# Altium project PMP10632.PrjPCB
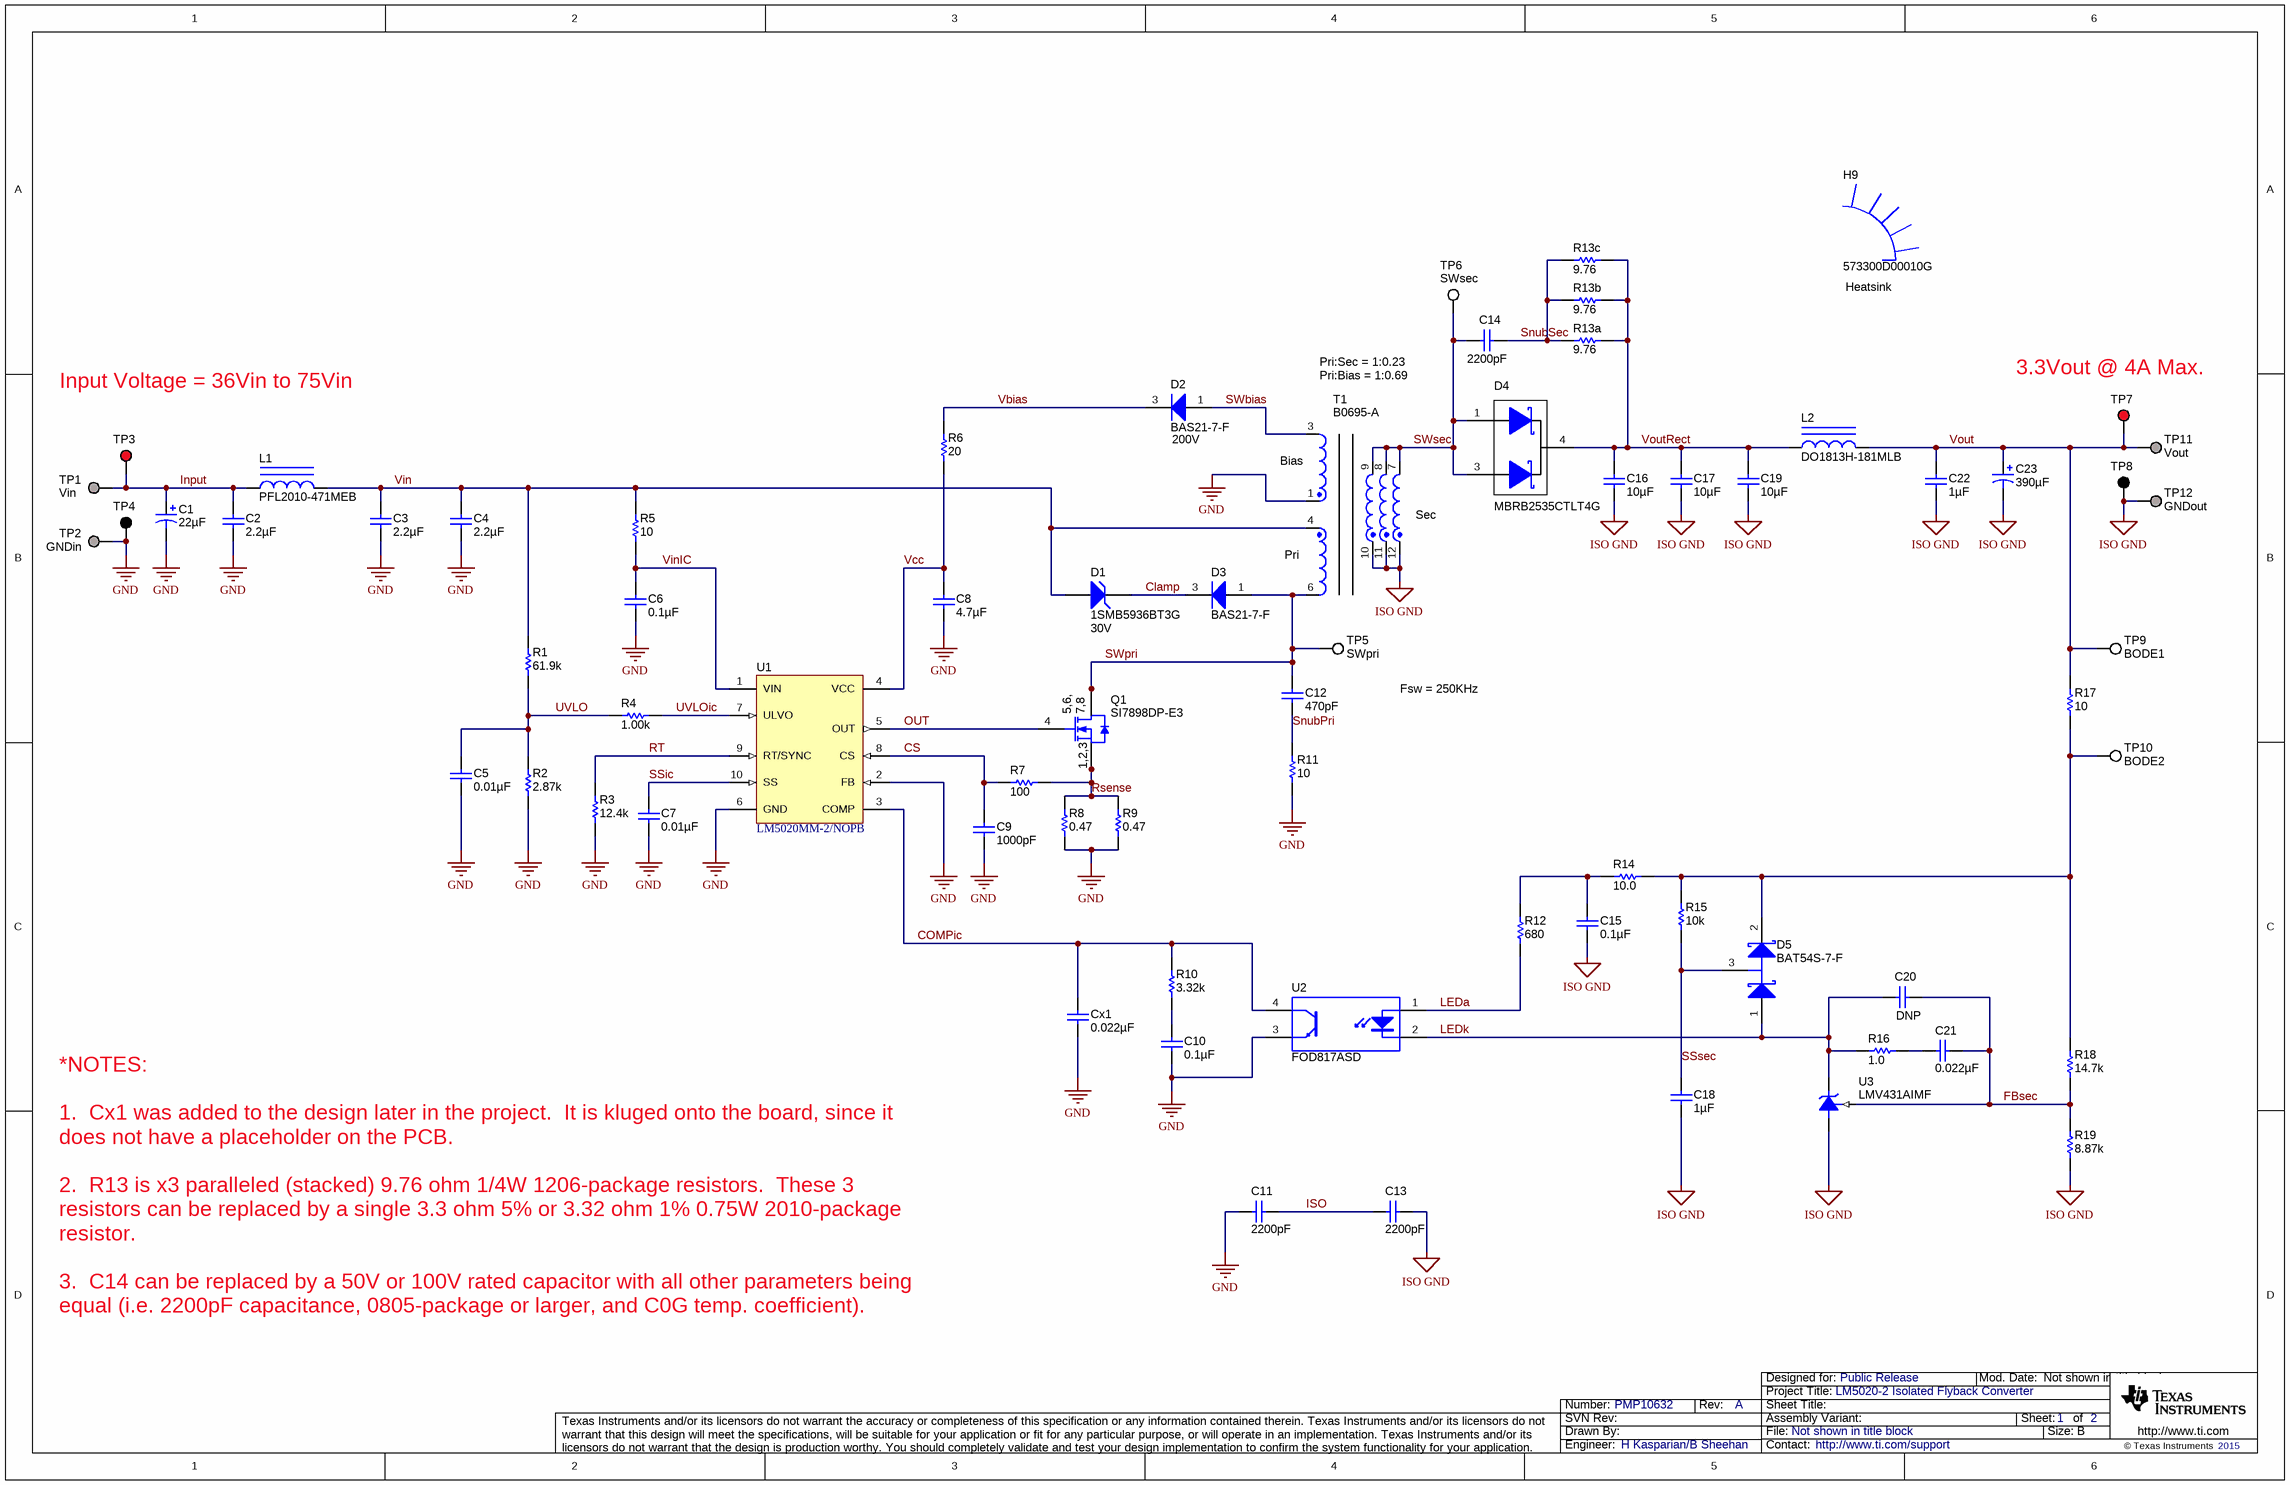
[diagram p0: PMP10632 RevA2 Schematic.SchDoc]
CopyrightYear: 2015; PCB_Layout: H Kasparian; PCB_Rev: A; PRJ_Customer: Public Release; PRJ_Engineer: H Kasparian/B Sheehan; PRJ_Number: PMP10632; PRJ_Title: LM5020-2 Isolated Flyback Converter; SCH_Rev: A; TechSupport: http://www.ti.com/support
2 sheets, 89 parts. Net scope: global (net labels, ports and power ports of the same name join across sheets).
Board file: PMP10632.PcbDoc
Sheets:
  PMP10632 RevA2 Schematic.SchDoc
  PMP10632_Hardware_ANSI-B.SchDoc

## Sheet PMP10632 RevA2 Schematic.SchDoc
size 431 x 279 mm; Date: Not shown in title block; ApprovedBy: Not shown in title block; CheckedBy: Not shown in title block; Author: Not shown in title block; CompanyName: Not shown in title block; Engineer: Not shown in title block; Organization: Not shown in title block; Address1: Not shown in title block; Address2: Not shown in title block; Address3: Not shown in title block; Address4: Not shown in title block; DocumentNumber: 1; Revision: A2; SheetNumber: 1; SheetTotal: 2; PageSetup: Record=PageOptions¦CenterHorizontal=True¦CenterVertical=True¦PrintScale=1.00¦XCorrection=1.00¦YCorrection=1.00¦PrintKind=0¦BorderSize=5000000¦LeftOffset=0¦BottomOffset=0¦Orientation=2¦PaperLength=1000¦PaperWidth=1000¦Scale=100¦PaperSource=15¦PrintQuality=600¦MediaType=1¦DitherType=10¦PaperKind=Letter¦PrintScaleMode=1

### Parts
C1  ValueDisplayed: 22µF  [SM_RADIAL_F]  (hidden comment: EEE-FK2A220P)
C2  ValueDisplayed: 2.2µF  [1210]  (hidden comment: GRM32ER72A225KA35L)
C3  ValueDisplayed: 2.2µF  [1210]  (hidden comment: GRM32ER72A225KA35L)
C4  ValueDisplayed: 2.2µF  [1210]  (hidden comment: GRM32ER72A225KA35L)
C5  ValueDisplayed: 0.01µF  [0603]  (hidden comment: GRM188R71E103KA01D)
C6  ValueDisplayed: 0.1µF  [0805_HV]  (hidden comment: C0805C104K1RACTU)
C7  ValueDisplayed: 0.01µF  [0603]  (hidden comment: GRM188R71E103KA01D)
C8  ValueDisplayed: 4.7µF  [0805_HV]  (hidden comment: GRM21BR71C475KA73L)
C9  ValueDisplayed: 1000pF  [0603]  (hidden comment: C0603C102J5GAC)
C10  ValueDisplayed: 0.1µF  [0603]  (hidden comment: 06035C104KAT2A)
C11  ValueDisplayed: 2200pF  [1206]  (hidden comment: VJ1206Y222KXGAT5Z)
C12  ValueDisplayed: 470pF  [0805_HV]  (hidden comment: GRM2165C2A471JA01D)
C13  ValueDisplayed: 2200pF  [1206]  (hidden comment: VJ1206Y222KXGAT5Z)
C14  2200pF  [TBD]
C15  ValueDisplayed: 0.1µF  [0603]  (hidden comment: GRM188R71E104KA01D)
C16  ValueDisplayed: 10µF  [1206]  (hidden comment: GRM31CR71E106KA12L)
C17  ValueDisplayed: 10µF  [1206]  (hidden comment: GRM31CR71E106KA12L)
C18  ValueDisplayed: 1µF  [0603]  (hidden comment: GRM188R71A105KA61D)
C19  ValueDisplayed: 10µF  [1206]  (hidden comment: GRM31CR71E106KA12L)
C20  DNP  [0603]
C21  ValueDisplayed: 0.022µF  [0603]  (hidden comment: GRM188R71H223KA01D)
C22  ValueDisplayed: 1µF  [0805_HV]  (hidden comment: GRM219R71E105KA88D)
C23  ValueDisplayed: 390µF  [CAPAE1030X1080]  (hidden comment: EEE-FPV391UAP)
Cx1  ValueDisplayed: 0.022µF  [0603]  (hidden comment: C0603C223K5RACTU)
D1  1SMB5936BT3G  value 30V  [SMB]
D2  BAS21-7-F  value 200V  [SOT-23]
D3  BAS21-7-F  [SOT-23]
D4  MBRB2535CTLT4G  [DDPAK]
D5  BAT54S-7-F  [SOT-23]
H9  573300D00010G  [HEATSINK_573300D00010G]
L1  PFL2010-471MEB  [PFL2010]
L2  DO1813H-181MLB  [DO1813H]
Q1  SI7898DP-E3  [PowerPAK_SO-8]
R1  ValueDisplayed: 61.9k  [1206]  (hidden comment: CRCW120661K9FKEA)
R2  ValueDisplayed: 2.87k  [0603]  (hidden comment: CRCW06032K87FKEA)
R3  ValueDisplayed: 12.4k  [0603]  (hidden comment: CRCW060312K4FKEA)
R4  ValueDisplayed: 1.00k  [0603]  (hidden comment: CRCW06031K00FKEA)
R5  ValueDisplayed: 10  [0805_HV]  (hidden comment: CRCW080510R0JNEA)
R6  ValueDisplayed: 20  [0805_HV]  (hidden comment: CRCW080520R0JNEA)
R7  ValueDisplayed: 100  [0603]  (hidden comment: CRCW0603100RFKEA)
R8  ValueDisplayed: 0.47  [1206]  (hidden comment: ERJ-8RQFR47V)
R9  ValueDisplayed: 0.47  [1206]  (hidden comment: ERJ-8RQFR47V)
R10  ValueDisplayed: 3.32k  [0603]  (hidden comment: CRCW06033K32FKEA)
R11  ValueDisplayed: 10  [2512]  (hidden comment: CRCW251210R0JNEG)
R12  ValueDisplayed: 680  [0603]  (hidden comment: CRCW0603680RJNEA)
R13a  ValueDisplayed: 9.76  [1206]  (hidden comment: CRCW12069R76FKEA)
R13b  ValueDisplayed: 9.76  [1206]  (hidden comment: CRCW12069R76FKEA)
R13c  ValueDisplayed: 9.76  [1206]  (hidden comment: CRCW12069R76FKEA)
R14  ValueDisplayed: 10.0  [0603]  (hidden comment: CRCW060310R0FKEA)
R15  ValueDisplayed: 10k  [0603]  (hidden comment: CRCW060310K0JNEA)
R16  ValueDisplayed: 1.0  [0603]  (hidden comment: CRCW06031R00JNEA)
R17  ValueDisplayed: 10  [0805_HV]  (hidden comment: CRCW080510R0JNEA)
R18  ValueDisplayed: 14.7k  [0603]  (hidden comment: CRCW060314K7FKEA)
R19  ValueDisplayed: 8.87k  [0603]  (hidden comment: CRCW06038K87FKEA)
T1  B0695-A  [B0695-A]
TP1  Vin  [Keystone1593-2]
TP2  GNDin  [Keystone1593-2]
TP3  (no value)  [Keystone5010]
TP4  (no value)  [Keystone5011]
TP5  SWpri  [Keystone5012]
TP6  SWsec  [Keystone5012]
TP7  (no value)  [Keystone5010]
TP8  (no value)  [Keystone5011]
TP9  BODE1  [Keystone5012]
TP10  BODE2  [Keystone5012]
TP11  Vout  [Keystone1593-2]
TP12  GNDout  [Keystone1593-2]
U1  LM5020MM-2/NOPB  [MUB10A_N]
U2  FOD817ASD  [N04C]
U3  LMV431AIMF  [MF03A_N]

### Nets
GND: C1.2(-) C2.2 C3.2 C4.2 C5.2 C6.2 C7.2 C8.2 C9.2 C10.2 C11.2 Cx1.2 R2.1 R3.1 R8.1 R9.1 R11.1 T1.1 TP2.1 TP4.1 U1.2(FB) U1.6(GND) U2.3(E)
ISO GND: C13.1 C15.2 C16.2 C17.2 C18.2 C19.2 C22.2 C23.2(-) R19.1 T1.10 T1.11 T1.12 TP8.1 TP12.1 U3.3(A)
Clamp: D1.1(K) D3.3(K)
COMPic: Cx1.1 R10.2 U1.3(COMP) U2.4(C)
CS: C9.1 R7.1 U1.8(CS)
FBsec: C20.1 C21.2 R18.1 R19.2 U3.1(REF)
Input: C1.1(+) C2.1 L1.1 TP1.1 TP3.1
ISO: C11.1 C13.2
LEDa: R12.1 U2.1(A)
LEDk: C20.2 D5.1(A) R16.2 U2.2(K) U3.2(K)
OUT: Q1.4(G) U1.5(OUT)
Rsense: Q1.1(S) Q1.2(S) Q1.3(S) R7.2 R8.2 R9.2
RT: R3.2 U1.9(RT/SYNC)
SnubPri: C12.2 R11.2
SnubSec: C14.1 R13a.2 R13b.2 R13c.2
SSic: C7.1 U1.10(SS)
SSsec: C18.1 D5.3(C) R15.1
SWbias: D2.1(A) T1.3
SWpri: C12.1 D3.1(A) Q1.5(D) Q1.6(D) Q1.7(D) Q1.8(D) Q1.9(D) T1.6 TP5.1
SWsec: C14.2 D4.1(A) D4.3(A) T1.7 T1.8 T1.9 TP6.1
UVLO: C5.1 R1.1 R2.2 R4.1
UVLOic: R4.2 U1.7(ULVO)
Vbias: D2.3(K) R6.1
Vcc: C8.1 R6.2 U1.4(VCC)
Vin: C3.1 C4.1 D1.2(A) L1.2 R1.2 R5.2 T1.4
VinIC: C6.1 R5.1 U1.1(VIN)
Vout: C22.1 C23.1(+) L2.2 R17.2 TP7.1 TP9.1 TP11.1
VoutRect: C16.1 C17.1 C19.1 D4.4(K) L2.1 R13a.1 R13b.1 R13c.1
NetC10_1: C10.1 R10.1
NetC15_1: C15.1 R12.2 R14.2
NetC21_1: C21.1 R16.1
NetD5_2: D5.2(K) R14.1 R15.2 R17.1 R18.2 TP10.1

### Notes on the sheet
- (near H9) Heatsink
- (near TP7) 3.3Vout @ 4A Max.
- Input Voltage = 36Vin to 75Vin
- Pri:Sec = 1:0.23
  Pri:Bias = 1:0.69
- (near T1) Bias
- (near T1) Pri
- (near T1) Sec
- Fsw = 250KHz
- *NOTES:
  1.  Cx1 was added to the design later in the project.  It is kluged onto the board, since it does not have a placeholder on the PCB.
  2.  R13 is x3 paralleled (stacked) 9.76 ohm 1/4W 1206-package resistors.  These 3 resistors can be replaced by a single 3.3 ohm 5% or 3.32 ohm 1% 0.75W 2010-package resistor.
  3.  C14 can be replaced by a 50V or 100V rated capacitor with all other parameters being equal (i.e. 2200pF capacitance, 0805-package or larger, and C0G temp. coefficient).

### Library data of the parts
C1 = EEE-FK2A220P: CAP, AL, 22 µF, 100 V, +/- 20%, 1.3 ohm, SMD; Manufacturer: Panasonic; Polarized: Y; CompType: Capacitor; Value: 22uF; U/M: EA; Cap_F: 0.000022; Tolerance_%: 20; Value1: 1.3 ohm; VDC_V: 100; Value2: 100V; ESR_ohm: 1.3; IRMS_A: 0.13; TaMin_C: -55; TaMax_C: 105; Cap_Case: F
C2-C4 = GRM32ER72A225KA35L: CAP, CERM, 2.2 µF, 100 V, +/- 10%, X7R, 1210; Manufacturer: MuRata; Polarized: N; CompType: Capacitor; Value: 2.2uF; U/M: EA; Cap_F: 0.0000022; Tolerance_%: 10; ESR_ohm: 0.007; Value1: 0.007 ohm; VDC_V: 100; Value2: 100V; IRMS_A: 4.4; TaMin_C: -55; TaMax_C: 125
C5 C7 = GRM188R71E103KA01D: CAP, CERM, 0.01 µF, 25 V, +/- 10%, X7R, 0603; Manufacturer: MuRata; Polarized: N; CompType: Capacitor; Value: 0.01uF; U/M: EA; Cap_F: 0.00000001; Tolerance_%: 10; Value1: Unknown; VDC_V: 25; Value2: 25V; TaMin_C: -55; TaMax_C: 125
C6 = C0805C104K1RACTU: CAP, CERM, 0.1 µF, 100 V, +/- 10%, X7R, 0805; Manufacturer: Kemet; Polarized: N; CompType: Capacitor; Value: 0.1uF; U/M: EA; Cap_F: 0.0000001; Tolerance_%: 10; ESR_ohm: 0.064; Value1: 0.064 ohm; VDC_V: 100; Value2: 100V; IRMS_A: 1.64; TaMin_C: -55; TaMax_C: 125; Cap_Case: 0805
C8 = GRM21BR71C475KA73L: CAP, CERM, 4.7 µF, 16 V, +/- 10%, X7R, 0805; Manufacturer: MuRata; Polarized: N; CompType: Capacitor; Value: 4.7uF; U/M: EA; Cap_F: 0.0000047; Tolerance_%: 10; ESR_ohm: 0.006; Value1: 0.006 ohm; VDC_V: 16; Value2: 16V; TaMin_C: -55; TaMax_C: 125; Cap_Case: 0805
C9 = C0603C102J5GAC: CAP, CERM, 1000 pF, 50 V, +/- 5%, C0G/NP0, 0603; Manufacturer: Kemet; Polarized: N; CompType: Capacitor; Value: 1000pF; U/M: EA; Cap_F: 0.000000001; Tolerance_%: 5; Value1: Unknown; VDC_V: 50; Value2: 50V; TaMin_C: -55; TaMax_C: 125
C10 = 06035C104KAT2A: CAP, CERM, 0.1 µF, 50 V, +/- 10%, X7R, 0603; Manufacturer: AVX; Polarized: N; CompType: Capacitor; Value: 0.1uF; U/M: EA; Cap_F: 0.0000001; Tolerance_%: 10; Value1: Unknown; VDC_V: 50; Value2: 50V; TaMin_C: -55; TaMax_C: 125
C11 C13 = VJ1206Y222KXGAT5Z: CAP, CERM, 2200 pF, 1000 V, +/- 10%, X7R, 1206; Manufacturer: Vishay-Vitramon; Polarized: N; CompType: Capacitor; Value: 2200pF; U/M: EA; Cap_F: 0.0000000022; Tolerance_%: 10; Value1: Unknown; VDC_V: 1000; Value2: 1000V; TaMin_C: -55; TaMax_C: 125
C12 = GRM2165C2A471JA01D: CAP, CERM, 470 pF, 100 V, +/- 5%, C0G/NP0, 0805; Manufacturer: MuRata; Polarized: N; CompType: Capacitor; Value: 470pF; U/M: EA; Cap_F: 0.00000000047; Tolerance_%: 5; Value1: Unknown; VDC_V: 100; Value2: 100V; TaMin_C: -55; TaMax_C: 125; Cap_Case: 0805
C14 = Capacitor: CAP, CERM, 2200pF, 250V, C0G, 5%, 0805; Manufacturer: TDK; PartNumber: CGA4J3C0G2E222J; Polarized: N; U/M: EA
C15 = GRM188R71E104KA01D: CAP, CERM, 0.1 µF, 25 V, +/- 10%, X7R, 0603; Manufacturer: MuRata; Polarized: N; CompType: Capacitor; Value: 0.1uF; U/M: EA; Cap_F: 0.0000001; Tolerance_%: 10; Value1: Unknown; VDC_V: 25; Value2: 25V; TaMin_C: -55; TaMax_C: 125
C16 C17 C19 = GRM31CR71E106KA12L: CAP, CERM, 10 µF, 25 V, +/- 10%, X7R, 1206; Manufacturer: MuRata; Polarized: N; CompType: Capacitor; Value: 10uF; U/M: EA; Cap_F: 0.00001; Tolerance_%: 10; Value1: Unknown; VDC_V: 25; Value2: 25V; TaMin_C: -55; TaMax_C: 125; Cap_Case: 2220
C18 = GRM188R71A105KA61D: CAP, CERM, 1 µF, 10 V, +/- 10%, X7R, 0603; Manufacturer: MuRata; Polarized: N; CompType: Capacitor; Value: 1uF; U/M: EA; Cap_F: 0.000001; Tolerance_%: 10; ESR_ohm: 0.011; Value1: 0.011 ohm; Value2: 10V; TaMin_C: -55; TaMax_C: 125
C20 = GRM1885C1H101JA01D: CAP, CERM, 100 pF, 50 V, +/- 5%, C0G/NP0, 0603; Manufacturer: MuRata; Polarized: N; CompType: Capacitor; Value: 100pF; U/M: EA; Cap_F: 0.0000000001; Tolerance_%: 5; Value1: Unknown; VDC_V: 50; Value2: 50V; TaMin_C: -55; TaMax_C: 125
C21 = GRM188R71H223KA01D: CAP, CERM, 0.022 µF, 50 V, +/- 10%, X7R, 0603; Manufacturer: MuRata; Polarized: N; CompType: Capacitor; Value: 0.022uF; U/M: EA; Cap_F: 0.000000022; Tolerance_%: 10; Value1: Unknown; VDC_V: 50; Value2: 50V; TaMin_C: -55; TaMax_C: 125
C22 = GRM219R71E105KA88D: CAP, CERM, 1 µF, 25 V, +/- 10%, X7R, 0805; Manufacturer: MuRata; Polarized: N; CompType: Capacitor; Value: 1uF; U/M: EA; Cap_F: 0.000001; Tolerance_%: 10; Value1: Unknown; VDC_V: 25; Value2: 25V; TaMin_C: -55; TaMax_C: 125; Cap_Case: 0805
C23 = EEE-FPV391UAP: CAP, AL, 390 µF, 35 V, +/- 20%, 0.08 ohm, SMD; Manufacturer: Panasonic; Polarized: Y; CompType: Capacitor; Value: 390uF; U/M: EA; Cap_F: 0.00039; Tolerance_%: 20; VDC_V: 35; Value2: 35V; ESR_ohm: 0.08; IRMS_A: 0.85; TaMin_C: -55; TaMax_C: 105; Cap_Case: 10x10.2mm
Cx1 = C0603C223K5RACTU: CAP, CERM, 0.022 µF, 50 V, +/- 10%, X7R, 0603; Manufacturer: Kemet; Polarized: N; CompType: Capacitor; Value: 0.022uF; U/M: EA; Cap_F: 0.000000022; Tolerance_%: 10; Value1: Unknown; VDC_V: 50; Value2: 50V; TaMin_C: -55; TaMax_C: 125
D1 = 1SMB5936BT3G: Diode, Zener, 30 V, 550 mW, SMB; Manufacturer: ON Semiconductor; SymbolCreator: a0412235; U/M: EA; Power_W: 0.55; Vz_V: 30; Value1: 0.55W; RJA_CperW: 226
D2 = BAS21-7-F: Diode, Switching, 200 V, 0.2 A, SOT-23; Manufacturer: Diodes Inc.; U/M: EA; Vf_V: 1.25; Value1: 0.2A; Value2: 1.25V; Io_A: 0.2; Vr_V: 200; TJmax_C: 150; RJC_CperW: 500
D3 = BAS21-7-F: Diode, Switching, 200 V, 0.2 A, SOT-23; Manufacturer: Diodes Inc.; U/M: EA; Vf_V: 1.25; Value: 200V; Value1: 0.2A; Value2: 1.25V; Io_A: 0.2; Vr_V: 200; TJmax_C: 150; RJC_CperW: 500
D4 = MBRB2535CTLT4G: Diode, Schottky, 35 V, 25 A, DDPAK; Manufacturer: ON Semiconductor; U/M: EA; Vf_V: 0.55; Value: 35V; Value1: 25A; Value2: 0.55V; Io_A: 25; Vr_V: 35; TJmax_C: 125; RJC_CperW: 1
D5 = BAT54S-7-F: Diode, Schottky, 30 V, 0.2 A, SOT-23; Manufacturer: Diodes Inc.; U/M: EA; Vf_V: 0.65; Value: 30V; Value1: 0.2A; Value2: 0.65V; Io_A: 0.2; Vr_V: 30; TJmax_C: 125
H9 = 573300D00010G: Heatsink, DDPAK/TO-263, SMT; Manufacturer: Aavid; SymbolCreator: a0412235
L1 = PFL2010-471MEB: Inductor, Shielded, Composite, 470 nH, 1.8 A, 0.06 ohm, SMD; Manufacturer: Coilcraft; Value: 470nH; Ind_H: 470.0E-9; Imax_A: 1.8; Irms: 1.9A @ 40C rise; Isat: 1.8A @ 30% inductance drop; DCR_ohm: 0.06; Value2: 1.8A
L2 = DO1813H-181MLB: Inductor, Drum Core, Ferrite, 180 nH, 10 A, 0.003 ohm, SMD; Manufacturer: Coilcraft; Value: 180nH; Ind_H: 180.0E-9; Imax_A: 10; Irms: 10A @ 40C rise; Isat: 14A @ 30% inductance drop; DCR_ohm: 0.003; Value2: 10A
Q1 = SI7898DP-E3: MOSFET, N-CH, 150 V, 3 A, PowerPAK SO-8; Manufacturer: Vishay-Siliconix; Alternate Manufacturer: None; U/M: EA; ChType: N; Value: 150V; VdsMax_V: 150; Value1: 0.076 ohm; Rdson45_ohm: 0.076; Value2: 17 nC; QgTyp_nC: 17; Vgs_V: 20; IdsMax_A: 3
R1 = CRCW120661K9FKEA: RES, 61.9 k, 1%, 0.25 W, 1206; Manufacturer: Vishay-Dale; CompType: Resistor; Value: 61.9k; Res_ohm: 61900; Value_Code: 61k9; Tolerance_%: 1; Power_W: 0.25; Value2: 0.25W; VDC_V: 200; TempCo: 100 ppm/C; EIA_Code: E96; U/M: EA
R2 = CRCW06032K87FKEA: RES, 2.87 k, 1%, 0.1 W, 0603; Manufacturer: Vishay-Dale; CompType: Resistor; Value: 2.87k; Res_ohm: 2870; Value_Code: 2k87; Tolerance_%: 1; Power_W: 0.1; Value2: 0.1W; VDC_V: 75; TempCo: 100 ppm/C; EIA_Code: E96; U/M: EA
R3 = CRCW060312K4FKEA: RES, 12.4 k, 1%, 0.1 W, 0603; Manufacturer: Vishay-Dale; CompType: Resistor; Value: 12.4k; Res_ohm: 12400; Value_Code: 12k4; Tolerance_%: 1; Power_W: 0.1; Value2: 0.1W; VDC_V: 75; TempCo: 100 ppm/C; EIA_Code: E96; U/M: EA
R4 = CRCW06031K00FKEA: RES, 1.00 k, 1%, 0.1 W, 0603; Manufacturer: Vishay-Dale; CompType: Resistor; Value: 1.00k; Res_ohm: 1000; Value_Code: 1k00; Tolerance_%: 1; Power_W: 0.1; Value2: 0.1W; VDC_V: 75; TempCo: 100 ppm/C; EIA_Code: E96; U/M: EA
R5 R17 = CRCW080510R0JNEA: RES, 10, 5%, 0.125 W, 0805; Manufacturer: Vishay-Dale; CompType: Resistor; Value: 10; Value_Code: 10R0; Tolerance_%: 5; Power_W: 0.125; Value2: 0.125W; VDC_V: 150; TempCo: 200 ppm/C; EIA_Code: E24; U/M: EA
R6 = CRCW080520R0JNEA: RES, 20, 5%, 0.125 W, 0805; Manufacturer: Vishay-Dale; CompType: Resistor; Value: 20; Value_Code: 20R0; Tolerance_%: 5; Power_W: 0.125; Value2: 0.125W; VDC_V: 150; TempCo: 200 ppm/C; EIA_Code: E24; U/M: EA
R7 = CRCW0603100RFKEA: RES, 100, 1%, 0.1 W, 0603; Manufacturer: Vishay-Dale; CompType: Resistor; Value: 100; Value_Code: 100R; Tolerance_%: 1; Power_W: 0.1; Value2: 0.1W; VDC_V: 75; TempCo: 100 ppm/C; EIA_Code: E96; U/M: EA
R8 R9 = ERJ-8RQFR47V: RES, 0.47, 1%, 0.25 W, 1206; Manufacturer: Panasonic; CompType: Resistor; Value: 0.47; Value_Code: R470; Tolerance_%: 1; Power_W: 0.25; Value2: 0.25W; TempCo: 250 ppm/C; EIA_Code: E96; U/M: EA
R10 = CRCW06033K32FKEA: RES, 3.32 k, 1%, 0.1 W, 0603; Manufacturer: Vishay-Dale; CompType: Resistor; Value: 3.32k; Res_ohm: 3320; Value_Code: 3k32; Tolerance_%: 1; Power_W: 0.1; Value2: 0.1W; VDC_V: 75; TempCo: 100 ppm/C; EIA_Code: E96; U/M: EA
R11 = CRCW251210R0JNEG: RES, 10, 5%, 1 W, 2512; Manufacturer: Vishay-Dale; CompType: Resistor; Value: 10; Value_Code: 10R0; Tolerance_%: 5; Power_W: 1; Value2: 1W; VDC_V: 500; TempCo: 200 ppm/C; EIA_Code: E24; U/M: EA
R12 = CRCW0603680RJNEA: RES, 680, 5%, 0.1 W, 0603; Manufacturer: Vishay-Dale; CompType: Resistor; Value: 680; U/M: EA; Value_Code: 680R; Tolerance_%: 5; Power_W: 0.1; Value2: 0.1W; VDC_V: 75; TempCo: 200 ppm/C; EIA_Code: E24
R13a R13b R13c = CRCW12069R76FKEA: RES, 9.76, 1%, 0.25 W, 1206; Manufacturer: Vishay-Dale; CompType: Resistor; Value: 9.76; Value_Code: 9R76; Tolerance_%: 1; Power_W: 0.25; Value2: 0.25W; VDC_V: 200; TempCo: 100 ppm/C; EIA_Code: E96; U/M: EA
R14 = CRCW060310R0FKEA: RES, 10.0, 1%, 0.1 W, 0603; Manufacturer: Vishay-Dale; CompType: Resistor; Value: 10.0; Res_ohm: 10; Value_Code: 10R0; Tolerance_%: 1; Power_W: 0.1; Value2: 0.1W; VDC_V: 75; TempCo: 100 ppm/C; EIA_Code: E96; U/M: EA
R15 = CRCW060310K0JNEA: RES, 10 k, 5%, 0.1 W, 0603; Manufacturer: Vishay-Dale; CompType: Resistor; Value: 10k; Res_ohm: 10000; Value_Code: 10k0; Tolerance_%: 5; Power_W: 0.1; Value2: 0.1W; VDC_V: 75; TempCo: 200 ppm/C; EIA_Code: E24; U/M: EA
R16 = CRCW06031R00JNEA: RES, 1.0, 5%, 0.1 W, 0603; Manufacturer: Vishay-Dale; CompType: Resistor; Value: 1.0; Res_ohm: 1; Value_Code: 1R00; Tolerance_%: 5; Power_W: 0.1; Value2: 0.1W; VDC_V: 75; TempCo: 200 ppm/C; EIA_Code: E24; U/M: EA
R18 = CRCW060314K7FKEA: RES, 14.7 k, 1%, 0.1 W, 0603; Manufacturer: Vishay-Dale; CompType: Resistor; Value: 14.7k; Res_ohm: 14700; Value_Code: 14k7; Tolerance_%: 1; Power_W: 0.1; Value2: 0.1W; VDC_V: 75; TempCo: 100 ppm/C; EIA_Code: E96; U/M: EA
R19 = CRCW06038K87FKEA: RES, 8.87 k, 1%, 0.1 W, 0603; Manufacturer: Vishay-Dale; CompType: Resistor; Value: 8.87k; Res_ohm: 8870; Value_Code: 8k87; Tolerance_%: 1; Power_W: 0.1; Value2: 0.1W; VDC_V: 75; TempCo: 100 ppm/C; EIA_Code: E96; U/M: EA
T1 = B0695-A: Pri:Sec = 1:0.23; Pri:Bias = 1:0.69 Transformer 1500Vrms Isolation; Manufacturer: Coilcraft; SymbolCreator: a0224881; Value: 105uH
TP1 TP2 TP11 TP12 = 1593-2: Terminal, Turret, TH, Double; Manufacturer: Keystone; CompType: Turret Terminal; U/M: EA
TP3 TP7 = 5010: Test Point, Multipurpose, Red, TH; Manufacturer: Keystone; CompType: Test Point Loop; U/M: EA
TP4 TP8 = 5011: Test Point, Multipurpose, Black, TH; Manufacturer: Keystone; CompType: Test Point Loop; U/M: EA
TP5 TP6 TP9 TP10 = 5012: Test Point, Multipurpose, White, TH; Manufacturer: Keystone; CompType: Test Point Loop; U/M: EA
U1 = LM5020MM-2/NOPB: 100V Current Mode PWM Controller, 10-pin MSOP, Pb-Free; Manufacturer: Texas Instruments; PackageTopMarking: ZXTT*SBNB; PowerWise: Y; CompType: Switcher
U2 = FOD817ASD: IC, Optocoupler, 5000V, 80-160% CTR; Manufacturer: Fairchild Semiconductor; U/M: EA
U3 = LMV431AIMF: Low-Voltage (1.24V) Adjustable Precision Shunt Regulator, 3-pin SOT-23; Manufacturer: Texas Instruments; PackageTopMarking: RLA*XTT; PowerWise: N; CompType: MiscPower

## Sheet PMP10632_Hardware_ANSI-B.SchDoc
size 431 x 279 mm; Date: Not shown in title block; ApprovedBy: Not shown in title block; CheckedBy: Not shown in title block; Author: Not shown in title block; CompanyName: Not shown in title block; Engineer: Not shown in title block; Organization: Not shown in title block; Address1: Not shown in title block; Address2: Not shown in title block; Address3: Not shown in title block; Address4: Not shown in title block; DocumentNumber: 2; Revision: Use project parameter SCH_Rev; SheetNumber: 2; SheetTotal: 2; PageSetup: Record=PageOptions¦CenterHorizontal=True¦CenterVertical=True¦PrintScale=1.00¦XCorrection=1.00¦YCorrection=1.00¦PrintKind=0¦BorderSize=5000000¦LeftOffset=0¦BottomOffset=0¦Orientation=2¦PaperLength=1000¦PaperWidth=1000¦Scale=100¦PaperSource=15¦PrintQuality=600¦MediaType=1¦DitherType=10¦PaperKind=Letter¦PrintScaleMode=1
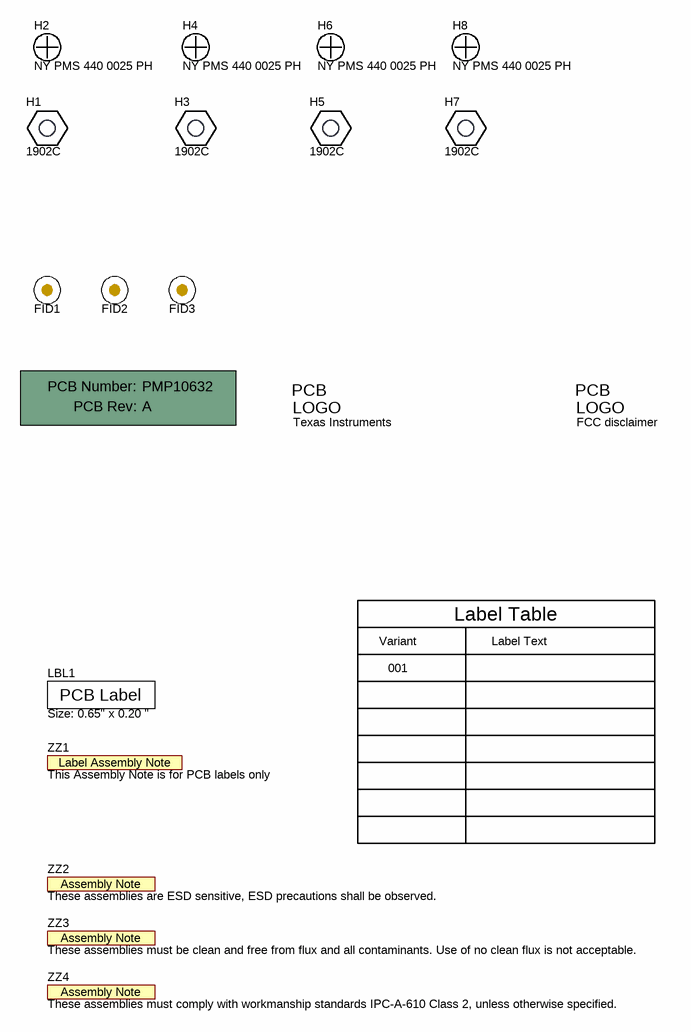
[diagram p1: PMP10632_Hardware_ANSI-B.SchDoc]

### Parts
!PCB1  Printed Circuit Board  (value not drawn)  (mechanical)
FID1  Fiducial  [Fiducial10-20]  (value not drawn)
FID2  Fiducial  [Fiducial10-20]  (value not drawn)
FID3  Fiducial  [Fiducial10-20]  (value not drawn)
H1  1902C  [Keystone_1902C]
H2  NY PMS 440 0025 PH  [NY PMS 440 0025 PH]
H3  1902C  [Keystone_1902C]
H4  NY PMS 440 0025 PH  [NY PMS 440 0025 PH]
H5  1902C  [Keystone_1902C]
H6  NY PMS 440 0025 PH  [NY PMS 440 0025 PH]
H7  1902C  [Keystone_1902C]
H8  NY PMS 440 0025 PH  [NY PMS 440 0025 PH]
LBL1  Size: 0.65" x 0.20 "  [Label_650x200]
Logo1  Texas Instruments  [TI_Stacked_SolderMask_Small]  (no BOM)
Logo3  FCC disclaimer  [FCC_disclaimer]  (no BOM)
ZZ1  This Assembly Note is for PCB labels only  [AssemblyNoteLabel]  (no BOM)
ZZ2  These assemblies are ESD sensitive, ESD precautions shall be observed.  [AssemblyNote]  (no BOM)
ZZ3  These assemblies must be clean and free from flux and all contaminants. Use of no clean flux is not acceptable.  [AssemblyNote]  (no BOM)
ZZ4  These assemblies must comply with workmanship standards IPC-A-610 Class 2, unless otherwise specified.  [AssemblyNote]  (no BOM)

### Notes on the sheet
- Variant
- Label Table
- Label Text
- 001

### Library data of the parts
!PCB1 = PCB: Manufacturer: Any; PartNumber: PMP10632; SymbolCreator: a0412235
FID1-FID3 = Fiducial: Fiducial mark.  There is nothing to buy or mount.; SymbolCreator: codlsc
H1 H3 H5 H7 = 1902C: Standoff, Hex, 0.5"L #4-40 Nylon; Manufacturer: Keystone; CompType: Hardware; SymbolCreator: a0412235
H2 H4 H6 H8 = NY PMS 440 0025 PH: Machine Screw, Round, #4-40 x 1/4, Nylon, Philips panhead; Manufacturer: B&F Fastener Supply; CompType: Hardware; SymbolCreator: codlsc; U/M: EA
LBL1 = THT-14-423-10: Thermal Transfer Printable Labels, 0.650" W x 0.200" H - 10,000 per roll; Manufacturer: Brady; SymbolCreator: a0412235; CompType: Label
Logo1 = TI_Logo: Texas Instrument Corporate Signature; SymbolCreator: a0412235
Logo3 = FCC_disclaimer: SymbolCreator: codlsc
ZZ1 = AssemblyNoteLabel: SymbolCreator: a0412235
ZZ2-ZZ4 = AssemblyNote: SymbolCreator: codlsc

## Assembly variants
001: not fitted C20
